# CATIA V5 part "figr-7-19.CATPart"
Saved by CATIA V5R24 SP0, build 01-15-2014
Part number: Part2
Bounding box of the stored display mesh (mm): x -50 to 50, y -65 to 65, z 0 to 28
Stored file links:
  D:\KAVITA\CATIA V5-6R2014 Project_ Kavita\CATIA V5-6R2014_partfiles\Partfiles\c07_catia_v5-6r2014_prt\figr-7-19.CATPart
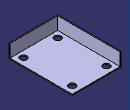
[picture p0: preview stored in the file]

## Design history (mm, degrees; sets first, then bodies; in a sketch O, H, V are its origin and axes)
Body1 (main body)
  Sketch1 on xy-plane, origin (0, 0, 0), H (1, 0, 0), V (0, 1, 0)
    line L1 (-50, 65) -> (50, 65)
    line L2 (50, 65) -> (50, -65)
    line L3 (50, -65) -> (-50, -65)
    line L4 (-50, -65) -> (-50, 65)
    axis line L5 (50, -65) -> (-50, 65)
    length L3 = 100
    length L2 = 130
    horizontal: L1 H, L3 H
    vertical: L2 V, L4 V
    midpoint: O L5
  Pad1: profile Sketch1, direction (0, 0, 1), length 28
  Shell1: ExtOffset 0, Face (face of Pad1; face of Pad1; face of Pad1), IntOffset 2
  Sketch2 on face of Pad1, origin (25.9302, -33.7092, 28), H (1, 0, 0), V (0, 1, 0)
    point P1 (9.0698, -16.2908)
    reference projected line E1 (-75.9302, -31.2908) -> (24.0698, -31.2908) from edge [face of Pad1 | face of Pad1]
    reference projected line E2 (24.0698, -31.2908) -> (24.0698, 98.7092) from edge [face of Pad1 | face of Pad1]
    distance P1 E1 = 15
    distance P1 E2 = 15
  Hole1: placed by Sketch2, at (35, -50, 28) direction (0, 0, -1), diameter 14, through (limit type 3)
  RectPattern1: of Hole1, direction 1 instances 2, spacing 100, along edge [face of Pad1 | face of Pad1], direction 2 instances 2, spacing 70, along edge [face of Pad1 | face of Pad1]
